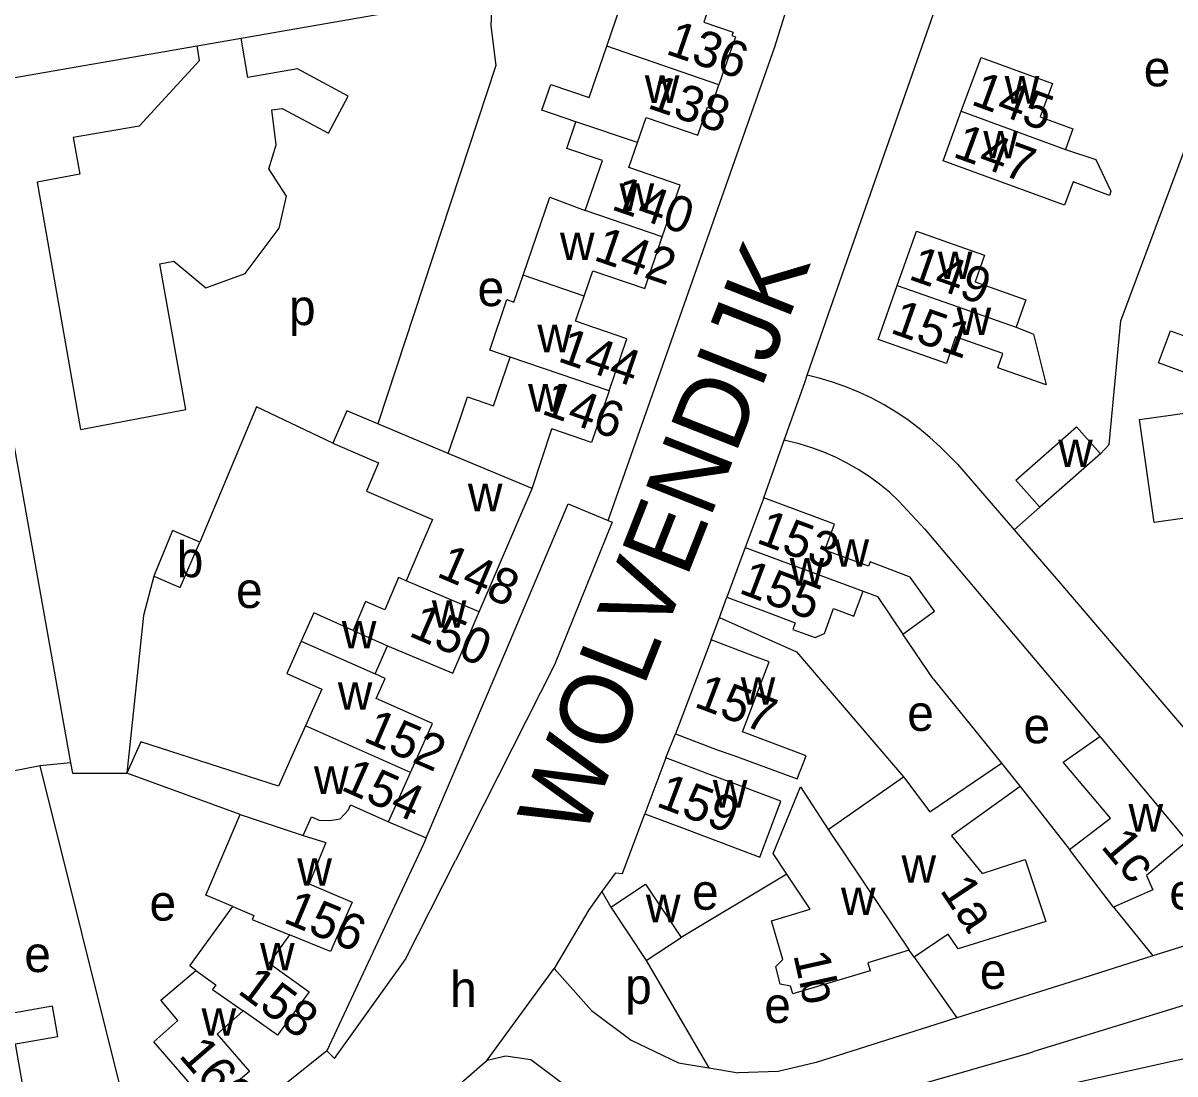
# Model space of a CAD drawing. Extents: x 162883 to 165538, y 383986 to 385172.
# Drawn here: x 164288.3 to 164417, y 384557.3 to 384674.8 of the extents above; entities that cross this region are included whole.
import ezdxf

# ---------------------------------------------------------------- set-up
doc = ezdxf.new("R2010")
doc.units = 0
for name, color, linetype in [('BLT_Basislijn', 7, 'Continuous'), ('BLT_Bebouwing', 7, 'Continuous'), ('BLT_Centroide', 7, 'Continuous'), ('BLT_Huisnummer', 7, 'Continuous'), ('BLT_Huisnummer_ tussenligend', 7, 'Continuous'), ('BLT_Onderverdeling_panden', 7, 'Continuous'), ('BLT_Straatnaam_hoofdweg', 7, 'Continuous'), ('BLT_Vlakafsluiter', 7, 'Continuous')]:
    doc.layers.add(name, color=color, linetype=linetype)

msp = doc.modelspace()

# ---------------------------------------------------------------- linework, layer by layer
at = {"layer": 'BLT_Basislijn'}
for p, q in [((164312.64, 384673.1), (164340.68, 384677.99)), ((164307.71, 384672.24), (164312.64, 384673.1)), ((164313.4, 384668.71), (164312.64, 384673.1)), ((164280.45, 384667.49), (164307.71, 384672.24)), ((164284.49, 384642.92), (164293.58, 384592.09)), ((164375.9, 384635.41), (164378.24, 384642.18)), ((164375.62, 384634.62), (164375.9, 384635.41)), ((164373.33, 384628.14), (164375.62, 384634.62)), ((164371.04, 384621.7), (164373.33, 384628.14)), ((164392.69, 384625.47), (164390.77, 384627.4)), ((164392.69, 384625.47), (164399.02, 384618.14)), ((164386.15, 384621.35), (164389.04, 384618.2)), ((164342.32, 384604.85), (164349.2, 384621.04)), ((164349.2, 384621.04), (164353.67, 384619.17)), ((164401.89, 384620.67), (164399.02, 384618.14)), ((164353.67, 384619.17), (164354.12, 384618.98)), ((164389.04, 384618.2), (164408.59, 384595.02)), ((164399.02, 384618.14), (164404.43, 384611.88)), ((164404.43, 384611.88), (164424.57, 384588.23)), ((164366.09, 384608.35), (164366.93, 384610.61)), ((164365.16, 384605.82), (164366.09, 384608.35)), ((164333.32, 384583.7), (164342.32, 384604.85)), ((164389.99, 384601.46), (164397.62, 384592.04)), ((164360.1, 384592.63), (164361.18, 384595.32)), ((164290.18, 384591.77), (164279.69, 384589.68)), ((164293.58, 384592.09), (164290.18, 384591.77)), ((164302.15, 384543.79), (164290.18, 384591.77)), ((164293.58, 384592.09), (164293.79, 384590.93)), ((164293.79, 384590.93), (164299.88, 384590.95)), ((164399.71, 384589.44), (164405.2, 384582.41)), ((164329.11, 384585.5), (164333.32, 384583.7)), ((164354.46, 384579.79), (164352.96, 384577.7)), ((164373.62, 384579.65), (164361.8, 384572.58)), ((164352.96, 384577.7), (164353.97, 384575.95)), ((164410.12, 384575.95), (164414.53, 384570.51)), ((164426.33, 384574.22), (164414.53, 384570.51)), ((164357.92, 384570.01), (164364.92, 384557.99)), ((164387.86, 384570.38), (164392.64, 384563.57)), ((164414.53, 384570.51), (164406, 384567.8)), ((164406, 384567.8), (164392.64, 384563.57)), ((164426.61, 384567.64), (164401.23, 384559.81)), ((164392.64, 384563.57), (164376.91, 384558.59)), ((164364.92, 384557.99), (164368.21, 384557.45))]:
    msp.add_line(p, q, dxfattribs=at)
for points in [[(164378.24, 384642.18), (164399.17, 384702.05), (164401.23, 384713.39)], [(164408.67, 384626.64), (164409.63, 384627.68), (164410.94, 384641.5), (164425.03, 384679.28), (164428.03, 384687.96)], [(164353.67, 384619.17), (164372.28, 384672.14), (164375.57, 384682.66)], [(164340.68, 384677.99), (164340.56, 384674.47), (164341.1, 384670.04), (164327.91, 384629.99)], [(164301.26, 384663.27), (164308, 384670.58), (164307.71, 384672.24)], [(164303.56, 384647.88), (164305.1, 384648.16), (164308.7, 384645.19), (164313.08, 384646.8), (164316.89, 384651.86), (164317.71, 384655.42), (164315.72, 384658.49), (164316.55, 384661.17), (164316.06, 384665.08), (164317.24, 384665.23), (164322.4, 384662.49), (164324.61, 384666.63), (164318.94, 384669.65), (164313.4, 384668.71)], [(164301.26, 384663.27), (164293.88, 384661.99), (164294.62, 384657.89), (164289.86, 384656.99), (164294.7, 384629.34), (164306.45, 384631.6), (164303.56, 384647.88)], [(164390.77, 384627.4), (164389.61, 384628.47), (164388.4, 384629.48), (164387.15, 384630.42), (164385.84, 384631.3), (164384.49, 384632.11), (164383.11, 384632.85), (164381.68, 384633.52), (164380.23, 384634.12), (164378.74, 384634.64), (164377.24, 384635.09), (164375.9, 384635.41)], [(164322.89, 384627.81), (164314.37, 384631.89), (164308.01, 384616.75)], [(164386.15, 384621.35), (164385.09, 384622.33), (164383.98, 384623.24), (164382.81, 384624.09), (164381.61, 384624.88), (164380.36, 384625.59), (164379.07, 384626.24), (164377.75, 384626.81), (164376.4, 384627.31), (164375.02, 384627.73), (164373.62, 384628.08), (164373.33, 384628.14)], [(164354.12, 384618.98), (164347.67, 384603.06), (164336.59, 384581.17)], [(164302.87, 384612.97), (164301.71, 384608.56), (164299.88, 384590.95)], [(164366.09, 384608.35), (164374.7, 384604.48), (164386.67, 384590.52)], [(164389.99, 384601.46), (164386.59, 384606.48)], [(164354.46, 384579.79), (164355.26, 384579.72), (164357.76, 384586.38)], [(164333.32, 384583.7), (164333.01, 384583.01), (164322.2, 384559.9)], [(164322.2, 384559.9), (164323.08, 384559.02), (164330.98, 384570.07), (164336.59, 384581.17)], [(164352.96, 384577.7), (164351.5, 384575.66), (164347.62, 384569.08)], [(164347.62, 384569.08), (164351.79, 384564.42), (164356.23, 384561.1), (164361.53, 384558.56), (164364.92, 384557.99)], [(164322.2, 384559.9), (164302.15, 384543.79)], [(164340.15, 384558.84), (164342.21, 384559.34), (164345, 384558.91), (164349.79, 384555.34)], [(164349.79, 384555.34), (164354.31, 384552.96), (164359.94, 384551.7), (164363.17, 384551.47), (164375.46, 384552.39), (164400.67, 384559.64), (164401.23, 384559.81)], [(164323.81, 384542.96), (164326.47, 384545.2), (164337.52, 384556.56), (164340.15, 384558.84)], [(164376.91, 384558.59), (164372.66, 384557.59), (164368.21, 384557.45)]]:
    msp.add_lwpolyline(points, dxfattribs=at)
at = {"layer": 'BLT_Bebouwing'}
for p, q in [((164335.78, 384626.68), (164337.15, 384630.66)), ((164345.15, 384622.74), (164347.36, 384629.42)), ((164371.04, 384621.7), (164368.98, 384616.16)), ((164368.98, 384616.16), (164366.93, 384610.61)), ((164365.16, 384605.82), (164361.18, 384595.32)), ((164327.61, 384602.04), (164329.01, 384605.17)), ((164360.1, 384592.63), (164357.76, 384586.38)), ((164389.62, 384586.6), (164397.62, 384592.04)), ((164397.62, 384592.04), (164399.71, 384589.44)), ((164312.54, 384586.33), (164299.88, 384590.95)), ((164329.11, 384585.5), (164331.57, 384590.99)), ((164378.24, 384584.63), (164386.67, 384590.52)), ((164386.67, 384590.52), (164389.62, 384586.6)), ((164372.09, 384581.96), (164375.14, 384589.39)), ((164375.14, 384589.39), (164378.24, 384584.63)), ((164399.71, 384589.44), (164392.01, 384583.94)), ((164392.01, 384583.94), (164395.46, 384579.7)), ((164373.62, 384579.65), (164372.09, 384581.96)), ((164376.22, 384575.74), (164373.62, 384579.65)), ((164353.97, 384575.95), (164357.84, 384578.52)), ((164357.84, 384578.52), (164361.8, 384572.58)), ((164353.97, 384575.95), (164357.92, 384570.01)), ((164371.9, 384574.43), (164376.22, 384575.74)), ((164373.18, 384570.12), (164371.9, 384574.43)), ((164357.92, 384570.01), (164361.8, 384572.58)), ((164391.67, 384572.93), (164387.86, 384570.38)), ((164387.29, 384571.15), (164382.68, 384569.74)), ((164387.86, 384570.38), (164387.29, 384571.15)), ((164372.4, 384569.32), (164373.18, 384570.12)), ((164382.68, 384569.74), (164382.93, 384568.84)), ((164372.89, 384567.34), (164372.4, 384569.32)), ((164382.93, 384568.84), (164374.31, 384566.27)), ((164374.02, 384567.11), (164372.89, 384567.34)), ((164374.31, 384566.27), (164374.02, 384567.11)), ((164431.59, 384562.05), (164414.48, 384558.22)), ((164414.48, 384558.22), (164402.26, 384555.48))]:
    msp.add_line(p, q, dxfattribs=at)
for points in [[(164353.51, 384672.2), (164357.21, 384683.03), (164366.11, 384680.1)], [(164366.11, 384680.1), (164364.33, 384674.9), (164367.61, 384673.77), (164367.48, 384673.38), (164367.88, 384673.24), (164366.04, 384667.87)], [(164350.06, 384663.74), (164346.26, 384665.04), (164347.24, 384667.92), (164351.54, 384666.45), (164353.51, 384672.2)], [(164393.12, 384664.92), (164395.33, 384670.93), (164400.04, 384669.21), (164403.31, 384668.01), (164401.94, 384664.29), (164405.6, 384662.95), (164404.75, 384660.65)], [(164356.93, 384661.43), (164357.89, 384664.24), (164363.67, 384662.26), (164364.74, 384665.38), (164365.14, 384665.24), (164366.04, 384667.87)], [(164405.61, 384657.02), (164404.65, 384654.41), (164395.79, 384657.66), (164391.09, 384659.39), (164393.12, 384664.92)], [(164351.1, 384653.84), (164353.02, 384659.42), (164349.05, 384660.78), (164350.06, 384663.74)], [(164359.71, 384650.89), (164361.69, 384656.66), (164355.97, 384658.62), (164356.93, 384661.43)], [(164404.75, 384660.65), (164408.15, 384659.52), (164409.84, 384655.98), (164409.68, 384655.52), (164405.61, 384657.02)], [(164344.15, 384646.62), (164347.14, 384655.33), (164351.1, 384653.84)], [(164350.99, 384644.27), (164351.96, 384647.1), (164357.74, 384645.12), (164359.71, 384650.89)], [(164385.96, 384645.46), (164388.1, 384651.52), (164392.85, 384649.84), (164395.72, 384648.83), (164394.67, 384645.86), (164400.34, 384643.86), (164399.83, 384642.41), (164399.25, 384640.78)], [(164342.7, 384637.45), (164340.42, 384638.23), (164342.35, 384643.87), (164343.12, 384643.6), (164344.15, 384646.62)], [(164353.78, 384633.69), (164355.76, 384639.48), (164350.02, 384641.45), (164350.99, 384644.27)], [(164399.25, 384640.78), (164401.18, 384639.99), (164402.61, 384634.33), (164397.2, 384636.24), (164397.76, 384637.84), (164392.49, 384639.69), (164391.45, 384636.73), (164383.83, 384639.41), (164385.96, 384645.46)], [(164432.12, 384640.58), (164430.07, 384635.03), (164426.03, 384636.52), (164424.82, 384633.23), (164420.13, 384634.96), (164415.16, 384636.79), (164416.49, 384640.39), (164420.99, 384638.73), (164422.92, 384643.97)], [(164337.15, 384630.66), (164337.95, 384632.99), (164340.83, 384632), (164342.7, 384637.45)], [(164353.78, 384633.69), (164351.79, 384627.9), (164347.36, 384629.42)], [(164327.91, 384629.99), (164324.45, 384631.45), (164322.89, 384627.81)], [(164422.52, 384622.06), (164420.99, 384621.85), (164421.27, 384619.89), (164414.67, 384618.96), (164413.05, 384630.47), (164416.78, 384630.99), (164421.73, 384631.69), (164422.23, 384628.2), (164426.62, 384628.82), (164427.47, 384622.76), (164422.52, 384622.06)], [(164335.78, 384626.68), (164327.91, 384629.99)], [(164401.89, 384620.67), (164399.23, 384623.69), (164406.01, 384629.66), (164408.67, 384626.64)], [(164322.89, 384627.81), (164328, 384625.61), (164326.65, 384622.46), (164334.01, 384619.3), (164332.68, 384616.21), (164331.07, 384612.45)], [(164408.67, 384626.64), (164401.89, 384620.67)], [(164339.24, 384608.97), (164345.15, 384622.74)], [(164386.59, 384606.48), (164390.14, 384609.04), (164387.4, 384612.83), (164382.93, 384614.55), (164382.74, 384614.06), (164377.87, 384615.87), (164378.95, 384618.77), (164371.04, 384621.7)], [(164308.01, 384616.75), (164304.98, 384618.06), (164302.87, 384612.97)], [(164302.87, 384612.97), (164305.83, 384611.69), (164308.01, 384616.75)], [(164331.07, 384612.45), (164330.23, 384612.8), (164328.68, 384609.19)], [(164366.93, 384610.61), (164371.61, 384608.87), (164374.57, 384607.75), (164374.29, 384607.01), (164376.79, 384606.09), (164377.82, 384606.56), (164378.84, 384609.33), (164381.11, 384608.48), (164381.42, 384609.3), (164382.15, 384611.27)], [(164382.15, 384611.27), (164383.74, 384610.69), (164386.59, 384606.48)], [(164328.68, 384609.19), (164326.54, 384610.11), (164325.16, 384606.89)], [(164325.16, 384606.89), (164320.77, 384608.85), (164319.35, 384605.69)], [(164329.01, 384605.17), (164336.31, 384602.13), (164339.24, 384608.97)], [(164319.35, 384605.69), (164317.74, 384602.07), (164321.65, 384600.32), (164319.83, 384596.23)], [(164361.18, 384595.32), (164365.85, 384593.55), (164367.7, 384592.91), (164374.79, 384590.29), (164375.77, 384592.87), (164368.68, 384595.56), (164371.64, 384603.36), (164369.83, 384604.04), (164365.16, 384605.82)], [(164331.57, 384590.99), (164334.02, 384596.49), (164327.74, 384599.28), (164328.73, 384601.5), (164327.61, 384602.04)], [(164319.83, 384596.23), (164318.61, 384593.5), (164316.82, 384589.49), (164301.43, 384594.42), (164299.88, 384590.95)], [(164405.2, 384582.41), (164409.78, 384585.89), (164404.52, 384592.16), (164408.59, 384595.02)], [(164408.59, 384595.02), (164418.37, 384583.33)], [(164372.95, 384587.8), (164368.4, 384589.52), (164364.78, 384590.87), (164360.1, 384592.63)], [(164370.61, 384581.55), (164372.57, 384586.79), (164372.95, 384587.8)], [(164311.7, 384576.04), (164308.71, 384577.31), (164312.54, 384586.33)], [(164319.57, 384583.97), (164320.51, 384586.05), (164321.36, 384585.68), (164322.55, 384585.64), (164323.71, 384585.83), (164324.62, 384586.85), (164324.87, 384587.4), (164329.11, 384585.5)], [(164357.76, 384586.38), (164362.44, 384584.62), (164370.61, 384581.55)], [(164319.57, 384583.97), (164322.11, 384583.17), (164320.23, 384578.55), (164325.03, 384576.51), (164322.62, 384571.01), (164318.05, 384572.85)], [(164418.37, 384583.33), (164413.82, 384579.48), (164414.54, 384577.89), (164410.12, 384575.95)], [(164395.46, 384579.7), (164400.25, 384581.3), (164402.58, 384574.36), (164392.78, 384571.28), (164391.67, 384572.93)], [(164410.12, 384575.95), (164405.2, 384582.41)], [(164307.56, 384568.89), (164306.89, 384569.38), (164311.7, 384576.04)], [(164318.05, 384572.85), (164315.77, 384569.68), (164320.23, 384566.48), (164316.69, 384561.63), (164312.88, 384564.36)], [(164312.88, 384564.36), (164309.96, 384561.76), (164313.56, 384557.6), (164309.06, 384553.75), (164305.78, 384557.53), (164302.87, 384560.89), (164305.55, 384563.29), (164303.67, 384565.56), (164307.56, 384568.89)], [(164288.53, 384554.29), (164287.41, 384560.68), (164292.15, 384561.51), (164291.56, 384564.87), (164285.43, 384563.8)]]:
    msp.add_lwpolyline(points, dxfattribs=at)
at = {"layer": 'BLT_Onderverdeling_panden'}
for p, q in [((164366.04, 384667.87), (164353.51, 384672.2)), ((164393.12, 384664.92), (164404.75, 384660.65)), ((164356.93, 384661.43), (164350.06, 384663.74)), ((164359.71, 384650.89), (164351.1, 384653.84)), ((164350.99, 384644.27), (164344.15, 384646.62)), ((164385.96, 384645.46), (164399.25, 384640.78)), ((164353.78, 384633.69), (164342.7, 384637.45)), ((164345.15, 384622.74), (164335.78, 384626.68)), ((164368.98, 384616.16), (164382.15, 384611.27)), ((164339.24, 384608.97), (164331.07, 384612.45)), ((164325.16, 384606.89), (164329.01, 384605.17)), ((164319.35, 384605.69), (164327.61, 384602.04)), ((164331.57, 384590.99), (164319.83, 384596.23)), ((164312.54, 384586.33), (164319.57, 384583.97)), ((164378.24, 384584.63), (164387.29, 384571.15))]:
    msp.add_line(p, q, dxfattribs=at)
for points in [[(164311.7, 384576.04), (164314.06, 384575.04), (164313.87, 384574.59), (164318.05, 384572.85)], [(164307.56, 384568.89), (164309.81, 384567.26), (164309.43, 384566.75), (164312.88, 384564.36)]]:
    msp.add_lwpolyline(points, dxfattribs=at)
at = {"layer": 'BLT_Vlakafsluiter'}
msp.add_line((164340.15, 384558.84), (164347.62, 384569.08), dxfattribs=at)

# ---------------------------------------------------------------- texts
at = {"layer": 'BLT_Centroide'}
for s, p in [('e', (164413.51, 384667.71)), ('w', (164357.75, 384665.86)), ('w', (164397.97, 384665.78)), ('w', (164395.58, 384659.66)), ('w', (164354.93, 384653.79)), ('w', (164348.27, 384648.28)), ('w', (164390.49, 384646.16)), ('e', (164339.06, 384643.14)), ('p', (164317.99, 384641.02)), ('w', (164392.6, 384639.91)), ('w', (164345.75, 384637.98)), ('w', (164344.71, 384631.36)), ('w', (164403.95, 384625.16)), ('w', (164337.98, 384620.22)), ('b', (164305.44, 384612.84)), ('w', (164378.95, 384614)), ('w', (164373.94, 384611.91)), ('e', (164312.07, 384609.4)), ('w', (164333.95, 384607.19)), ('w', (164323.89, 384604.87)), ('w', (164323.44, 384598.02)), ('w', (164368.47, 384598.59)), ('e', (164387.08, 384595.66)), ('e', (164400.07, 384594.27)), ('w', (164320.78, 384588.61)), ('w', (164365.35, 384587.09)), ('w', (164411.81, 384584.41)), ('w', (164318.92, 384578.34)), ('w', (164386.44, 384578.69)), ('e', (164363.03, 384575.67)), ('e', (164416.37, 384575.69)), ('e', (164302.4, 384574.45)), ('w', (164357.88, 384574.27)), ('w', (164379.67, 384575.08)), ('e', (164288.41, 384568.7)), ('w', (164314.75, 384568.89)), ('e', (164395.19, 384566.82)), ('h', (164336, 384564.8)), ('p', (164355.56, 384565.15)), ('e', (164371.11, 384563.01)), ('w', (164308.22, 384561.58))]:
    msp.add_text(s, height=4, dxfattribs=at).set_placement(p)
at = {"layer": 'BLT_Huisnummer'}
for s, rotation, p in [('136', 341.0755, (164359.96, 384671.38)), ('145', 339.8349, (164394.08, 384665.73)), ('147', 339.8329, (164392.05, 384659.88)), ('140', 341.0817, (164353.88, 384653.99)), ('149', 340.5827, (164387.09, 384646.2)), ('151', 340.5824, (164385.05, 384640.2)), ('146', 341.0715, (164346.08, 384631.14)), ('153', 339.6474, (164370.08, 384616.74)), ('148', 336.7906, (164334.35, 384612.98)), ('155', 339.2307, (164368.13, 384611.13)), ('150', 336.7906, (164331.24, 384606.33)), ('157', 339.22, (164363.13, 384598.42)), ('152', 336.7906, (164326.15, 384594.56)), ('154', 335.934, (164323.65, 384589.11)), ('159', 339.4201, (164358.89, 384587.28)), ('1c', 309.9018, (164408.62, 384582.71)), ('1a', 303.833, (164390.65, 384577.84)), ('156', 337.3589, (164317.21, 384574.32)), ('1b', 282.6257, (164374.33, 384570.63)), ('160', 310.8936, (164305.57, 384559.32))]:
    msp.add_text(s, height=4, rotation=rotation, dxfattribs=at).set_placement(p)
at = {"layer": 'BLT_Huisnummer_ tussenligend'}
for s, rotation, p in [('138', 341.0755, (164357.92, 384665.33)), ('142', 341.0817, (164351.9, 384648.33)), ('144', 341.0817, (164347.89, 384637.02)), ('158', 323.3924, (164312.11, 384566.42))]:
    msp.add_text(s, height=4, rotation=rotation, dxfattribs=at).set_placement(p)
at = {"layer": 'BLT_Straatnaam_hoofdweg'}
msp.add_text('WOLVENDIJK', height=8, rotation=68.4706, dxfattribs=at).set_placement((164350.84, 384583.34))

doc.saveas('drawing.dxf')
